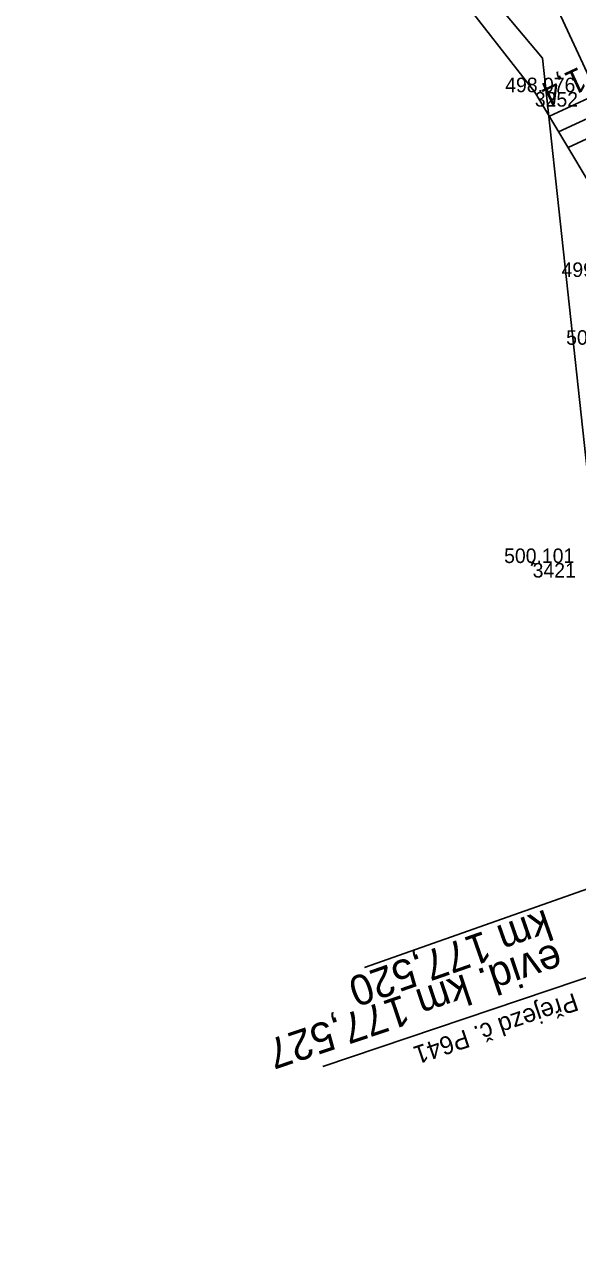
# Model space of a CAD drawing. Extents: x -1234191 to 23050, y -1290331 to -741191.
# Drawn here: x -864841.1 to -864795.4, y -1103617.8 to -1103515.6 of the extents above; entities that cross this region are included whole.
import ezdxf

# ---------------------------------------------------------------- set-up
doc = ezdxf.new("R2010")
doc.units = 0
for name, color, linetype in [('Vrstva 3', 7, 'Continuous'), ('Vrstva 4', 7, 'Continuous'), ('Vrstva 48', 7, 'Continuous'), ('Vrstva 49', 7, 'Continuous'), ('Vrstva 53', 7, 'Continuous'), ('Vrstva 60', 7, 'Continuous'), ('Vrstva 61', 7, 'Continuous')]:
    doc.layers.add(name, color=color, linetype=linetype)

msp = doc.modelspace()

# ---------------------------------------------------------------- linework, layer by layer
at = {"layer": 'Vrstva 3'}
msp.add_line((-864812.99, -1103593.46), (-864765.03, -1103576.48), dxfattribs=at)
at = {"layer": 'Vrstva 4'}
msp.add_line((-864816.44, -1103601.63), (-864763.18, -1103583.68), dxfattribs=at)
at = {"layer": 'Vrstva 48'}
for p, q in [((-864793.78, -1103521.3), (-864797.72, -1103523.13)), ((-864793.14, -1103522.66), (-864796.95, -1103524.43)), ((-864792.51, -1103524.02), (-864796.17, -1103525.72))]:
    msp.add_line(p, q, dxfattribs=at)
at = {"layer": 'Vrstva 49'}
for p, q in [((-864799.34, -1103559.95), (-864798.87, -1103560.13)), ((-864799.01, -1103559.81), (-864799.19, -1103560.28))]:
    msp.add_line(p, q, dxfattribs=at)
for points in [[(-864840.88, -1103428.13), (-864832.48, -1103443.19), (-864818.88, -1103470.42), (-864807.26, -1103494.15), (-864797.12, -1103514.11), (-864787.53, -1103534.72), (-864777.28, -1103560.25), (-864767.99, -1103579.5), (-864768.77, -1103583.18), (-864781.74, -1103586.59)], [(-864798.92, -1103521.15), (-864805.57, -1103512.63), (-864815.79, -1103498.19), (-864822.36, -1103485.1), (-864826.41, -1103476.66)], [(-864781.41, -1103556.37), (-864791.27, -1103536.35), (-864791.79, -1103533.03), (-864798.92, -1103521.15)]]:
    msp.add_lwpolyline(points, dxfattribs=at)
at = {"layer": 'Vrstva 53'}
msp.add_lwpolyline([(-864851.8, -1103965.2), (-864832.93, -1103934.25), (-864802.44, -1103886.38), (-864769.72, -1103812.69), (-864751.48, -1103715.25), (-864751.19, -1103685.96), (-864767.18, -1103674.13), (-864782.08, -1103622.93), (-864787.15, -1103586.96), (-864794.59, -1103552.36), (-864798.3, -1103518.33), (-864820.12, -1103492.38), (-864862.25, -1103399.25), (-864883.05, -1103347.48), (-864889.03, -1103323.28), (-864892.77, -1103263.78)], dxfattribs=at)
at = {"layer": 'Vrstva 60'}
for p, q in [((-864798.92, -1103521.15), (-864798.92, -1103521.15)), ((-864799.1, -1103560.04), (-864799.1, -1103560.04))]:
    msp.add_line(p, q, dxfattribs=at)

# ---------------------------------------------------------------- texts
at = {"layer": 'Vrstva 3'}
msp.add_text('km 177,520', height=2.5, rotation=199.29, dxfattribs=at).set_placement((-864798.03, -1103588.62))
at = {"layer": 'Vrstva 4'}
for s, height, p in [('evid. km 177,527', 2.5, (-864797.15, -1103591.4)), ('Přejezd č. P641', 1.5, (-864795.66, -1103595.52))]:
    msp.add_text(s, height=height, rotation=198.6243, dxfattribs=at).set_placement(p)
at = {"layer": 'Vrstva 48'}
msp.add_text('1,4', height=2, rotation=204.9517, dxfattribs=at).set_placement((-864795.26, -1103519.02))
at = {"layer": 'Vrstva 60'}
for s, p in [('3252', (-864798.92, -1103522.34)), ('3421', (-864799.1, -1103561.24))]:
    msp.add_text(s, height=1.2, dxfattribs=at).set_placement(p)
at = {"layer": 'Vrstva 61'}
for s, p in [('498.076', (-864801.37, -1103521.15)), ('499.657', (-864796.71, -1103536.41)), ('500.440', (-864796.33, -1103542.01)), ('500.101', (-864801.46, -1103560.04))]:
    msp.add_text(s, height=1.2, dxfattribs=at).set_placement(p)

doc.saveas('drawing.dxf')
